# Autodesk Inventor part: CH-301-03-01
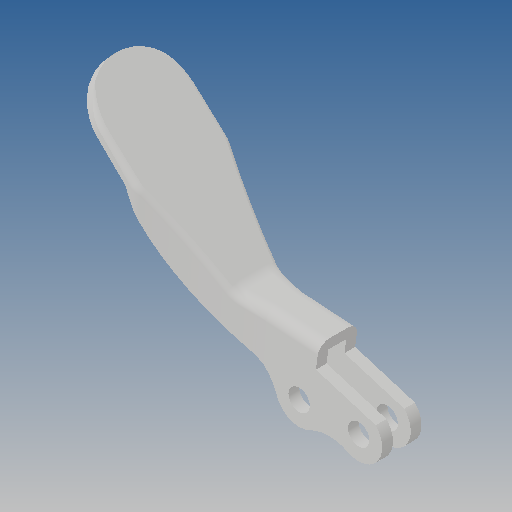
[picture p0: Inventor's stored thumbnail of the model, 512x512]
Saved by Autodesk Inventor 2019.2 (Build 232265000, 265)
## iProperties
Created: 2012-09
Part Number: CH-301-03-01
Material: Ogólny
Document SubType Name: Modeling
Designer: CADENGINEERING4
Density: 1 g/cm^3
Appearance: Domyślna
Author: CADENGINEERING4
Revision Number: ÈÎºÎ
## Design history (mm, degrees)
feature "Ô²½Ç34"
node "Bryła1"
